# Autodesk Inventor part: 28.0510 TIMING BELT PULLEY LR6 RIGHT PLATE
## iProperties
Created: 2007-06
Part Number: 28.0510 TIMING BELT PULLEY LR6 RIGHT PLATE
Document SubType Name: Modeling
Designer: Andy Moles
Material: Aluminum-6061
Mass: 286.088 g
Surface Area: 351.443 cm^2
Volume: 105.567 cm^3
Density: 2.71 g/cm^3
Author: Andy Moles
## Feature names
1. Extrusion1
2. Hole1
3. Hole2
4. Extrusion2
5. Extrusion3
6. Extrusion4
7. Extrusion5
8. Extrusion6
9. Fillet1
10. Extrusion7
11. Extrusion8
12. Extrusion9
13. Extrusion10
14. Hole3
15. Extrusion11
16. Extrusion12
17. Extrusion13
18. Hole4
19. Extrusion14
20. Extrusion15
21. Extrusion16
22. Mirror1
